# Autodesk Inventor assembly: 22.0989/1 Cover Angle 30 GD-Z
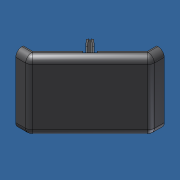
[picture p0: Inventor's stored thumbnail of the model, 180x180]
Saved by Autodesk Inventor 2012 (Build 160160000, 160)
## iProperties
Created: 2017-01
Part Number: 22.0989/1 Cover Angle 30 GD-Z
Document SubType Name: Assembly
Designer: Admin
Description: Cover Angle 30 GD-Z
Author: Admin
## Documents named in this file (3)
- C:\Andys Backup Data\ANDY'S INVENTOR\INVENTOR LIBRARIES\PARTS LIBRARY\30 SERIES\22.0989_1 Cover Angle 30 GD-Z.iam
- C:\Andys Backup Data\ANDY'S INVENTOR\INVENTOR LIBRARIES\PARTS LIBRARY\30 SERIES\SUBCOMPONENTS\22.0989_1 ANGLE 30 GD-Z COVER INSERT.ipt
- C:\Andys Backup Data\ANDY'S INVENTOR\INVENTOR LIBRARIES\PARTS LIBRARY\30 SERIES\SUBCOMPONENTS\22.0989_1 ANGLE 30 GD-Z COVER OUTER.ipt
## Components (2 placed, 2 different names)
1. 22.0989_1 ANGLE 30 GD-Z COVER OUTER:1 — Flush:1, Mate:1, Mate:2
2. 22.0989_1 ANGLE 30 GD-Z COVER INSERT:1 — Flush:1, Mate:1, Mate:2
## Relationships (3: Mate 2, Flush 1)
- Flush:1: 22.0989_1 ANGLE 30 GD-Z COVER OUTER:1 ↔ 22.0989_1 ANGLE 30 GD-Z COVER INSERT:1
- Mate:1: 22.0989_1 ANGLE 30 GD-Z COVER OUTER:1 ↔ 22.0989_1 ANGLE 30 GD-Z COVER INSERT:1
- Mate:2: 22.0989_1 ANGLE 30 GD-Z COVER OUTER:1 ↔ 22.0989_1 ANGLE 30 GD-Z COVER INSERT:1
